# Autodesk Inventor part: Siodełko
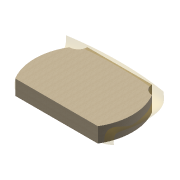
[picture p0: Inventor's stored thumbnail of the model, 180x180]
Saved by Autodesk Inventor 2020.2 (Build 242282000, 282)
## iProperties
Created: 2009-12
Part Number: Siodełko
Document SubType Name: Modeling
Designer: F.Stasiak
Density: 1 g/cm^3
Material: Ogólny
Appearance: Drewno (sklejka gat. B)
Manager: www.cadconsulting.pl
Company: Fabian Stasiak CAD Consulting
Author: F.Stasiak
Subject: Zbiór ćwiczeń. Autodesk Inventor 2020. Kurs podstawowy
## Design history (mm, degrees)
sketch "Sketch1"
  geometry: L1 (-275, 210)-(-215, 210); L2 (275, 210)-(275, 150); L3 (275, -210)-(-275, -210); L4 (-275, -210)-(-275, 150); L5 (-215, 210)-(215, 210); L6 (-275, 150)-(-275, 210); L7 (215, 210)-(275, 210); L8 (275, 150)-(275, -210); L9 (-275, 210)-(275, -210); A1 r 60 centre (-275, 210) between (-275, 150) and (-215, 210); A2 r 60 centre (275, 210) between (215, 210) and (275, 150); A3 r 350 centre (25.167, -30) between (-275, 150) and (-275, -210); A4 r 350 centre (-25.167, -30) between (275, -210) and (275, 150); 2 further points
  constraints: 18 end point, 8 point on circle, 7 parallel, 6 perpendicular, 4 centre point, 3 coincident, 3 horizontal, 2 equal radius, 1 midpoint, 1 point on line
  dimensions: "d0" = 550 distance of L3.start L3.end; "d1" = 420 distance of L3.end L1.start; "d2" = 120 diameter of A1; "d18" = 350 radius of A4
extrude "Extrusion1" new body sketch "Sketch1" stored distance "d4" = 100; taper "d5" = 0 deg
sketch "Sketch2"
  geometry: L1 (200.051, 19.746)-(217.668, 131.052); L2 (-165.069, -155.287)-(-178.682, 39.299); L3 (87.568, -19.861)-(172.459, -8.843); A1 r 805.113 centre (-586.354, 201.26) between (200.581, 31.143) and (214.652, 120.049); A2 r 306.275 centre (133.653, -36.619) between (-167.695, 18.093) and (-157.142, -132.757); A3 r 182.226 centre (106.557, 166.358) between (96.238, -15.575) and (162.982, -6.912); 5 further points
  constraints: 6 end point, 6 midpoint, 3 centre point, 3 point on circle, 10 other
workplane "Work Plane1"
workplane "Work Plane2"
workplane "Work Plane4"
workplane "Work Plane5"
sketch "Sketch3"
  geometry: L1 (-330.199, -13.181)-(330.199, -13.181); L2 (330.199, -13.181)-(330.199, 13.181); L3 (330.199, 13.181)-(-330.199, 13.181); L4 (-330.199, 13.181)-(-330.199, -13.181); L5 (0, -13.181)-(0, 13.181); 9 further points
  constraints: 10 end point, 4 symmetric about line, 3 midpoint, 2 parallel, 2 point on line, 1 horizontal, 1 horizontal alignment, 1 perpendicular, 1 vertical alignment, 8 other
sketch "Sketch4"
  geometry: L1 (328.132, 17.215)-(-328.132, 17.215); L2 (-328.132, 17.215)-(-328.132, -17.215); L3 (-328.132, -17.215)-(328.132, -17.215); L4 (328.132, -17.215)-(328.132, 17.215); L5 (0, 17.215)-(0, -17.215); 9 further points
  constraints: 10 end point, 4 symmetric about line, 3 midpoint, 2 parallel, 2 point on line, 1 coincident, 1 horizontal, 1 perpendicular, 8 other
sketch "Sketch5"
  geometry: L1 (328.208, 19.979)-(-328.208, 19.979); L2 (-328.208, 19.979)-(-328.208, -19.979); L3 (-328.208, -19.979)-(328.208, -19.979); L4 (328.208, -19.979)-(328.208, 19.979); L5 (0, -19.979)-(0, 19.979); L6 (0, -19.979)-(0, 19.979); 11 further points
  constraints: 12 end point, 5 midpoint, 4 symmetric about line, 2 parallel, 2 perpendicular, 1 coincident, 1 horizontal, 8 other
sketch "Sketch6"
  geometry: L1 (0, 0)-(0, -34.853); 3 further points
  constraints: 2 end point, 1 symmetric about line, 1 vertical, 3 other
feature "LoftSrf1" sketch "Sketch3", "Sketch4", "Sketch5", "Sketch6" dims "d6" = 0, "d7" = 90 deg, "d8" = 0, "d9" = 90 deg, "d10" = 0, "d11" = 90 deg, "d12" = 0, "d13" = 90 deg, "d14" = 0, "d15" = 90 deg
body "Solid1"
body "Srf1"
